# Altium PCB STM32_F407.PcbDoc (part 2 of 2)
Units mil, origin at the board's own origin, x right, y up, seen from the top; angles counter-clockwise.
Board outline 2935.42 x 3745.42 mil, 2 copper layers (TopLayer, BottomLayer); 75 components, 133 nets, 531 pads, 175 vias.
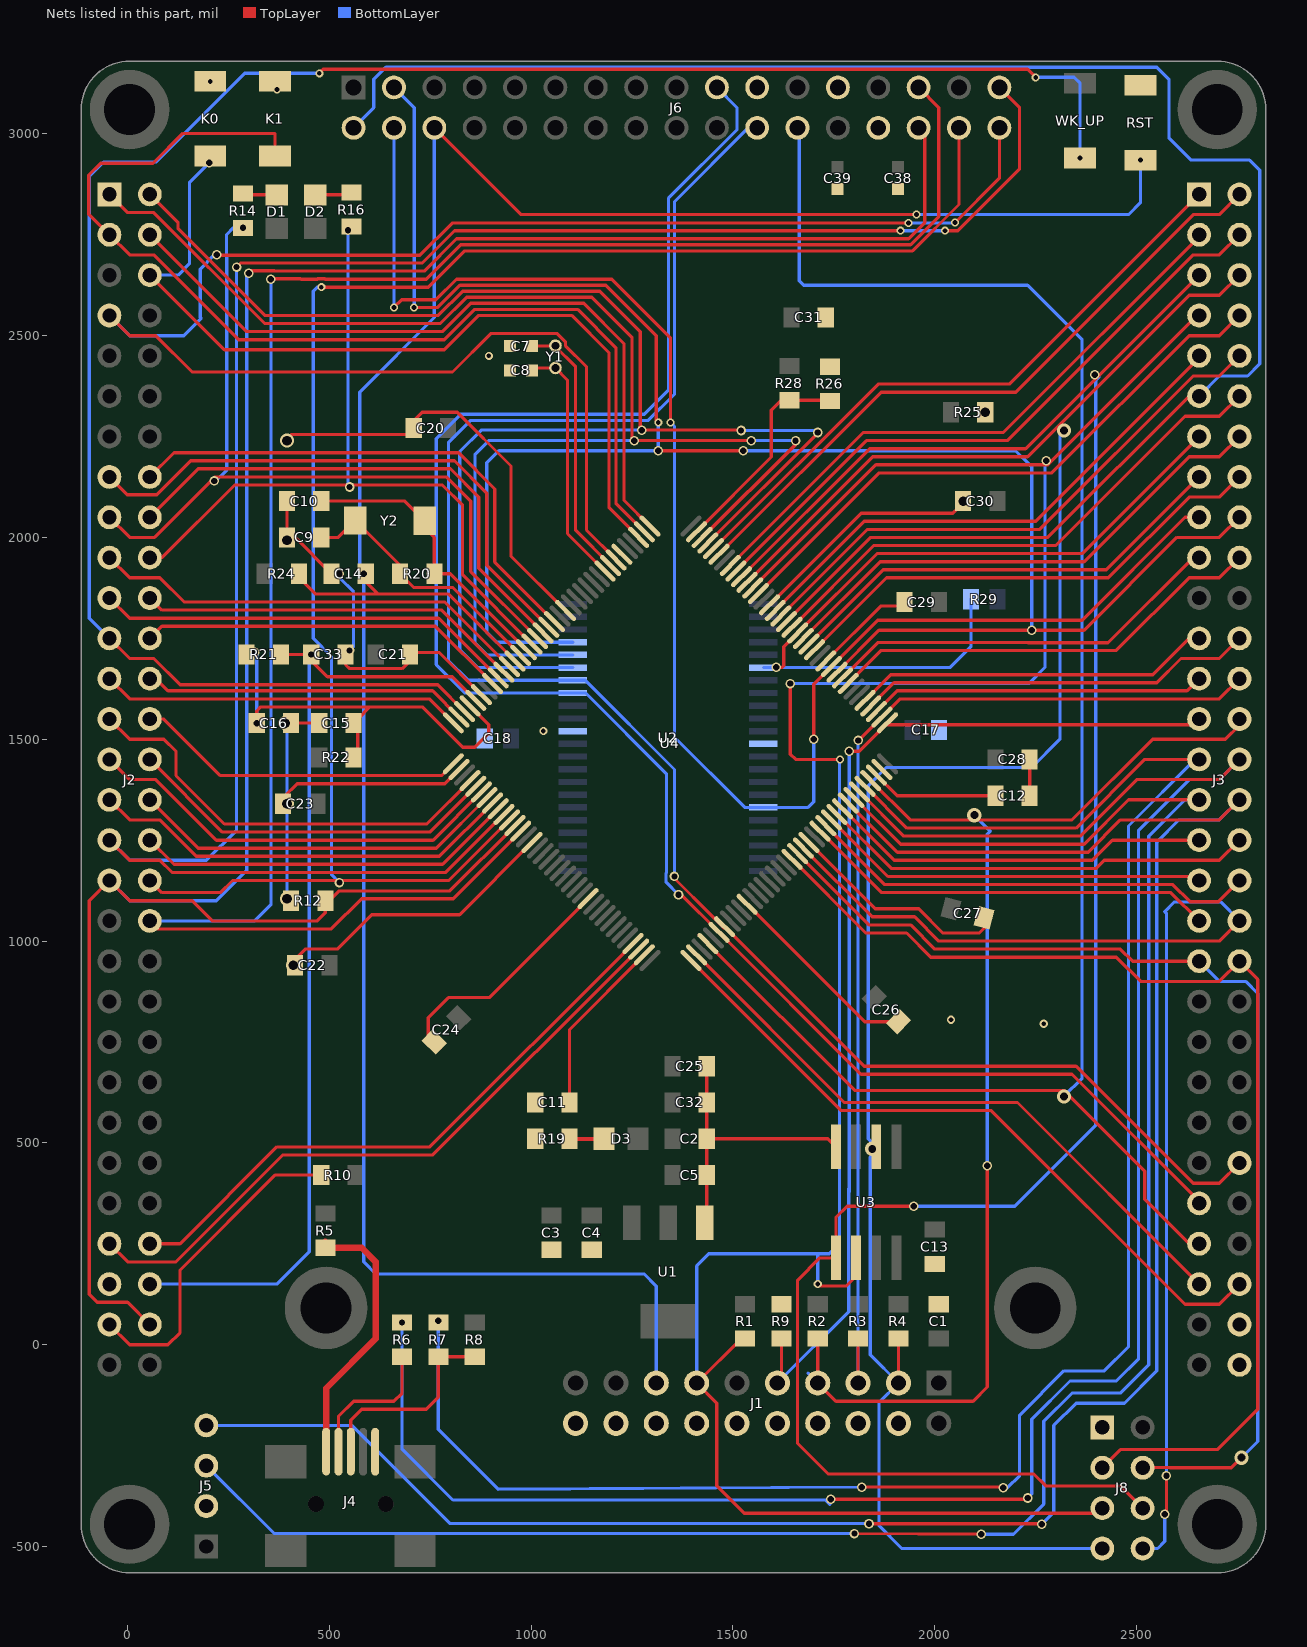
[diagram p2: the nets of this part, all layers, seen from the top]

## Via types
v1: diameter 23.62, hole 15.75, TopLayer to BottomLayer, 92 vias
v2: diameter 20, hole 12, TopLayer to BottomLayer, 62 vias
v3: diameter 35.43, hole 19.68, TopLayer to BottomLayer, 11 vias
v4: diameter 35.43, hole 23.62, TopLayer to BottomLayer, 10 vias

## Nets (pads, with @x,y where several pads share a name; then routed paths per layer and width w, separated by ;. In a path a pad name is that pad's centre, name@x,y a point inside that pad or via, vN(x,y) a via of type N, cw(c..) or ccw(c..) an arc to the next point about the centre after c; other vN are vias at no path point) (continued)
FSMC_D14: J3.51 J6.19 U2.37 U4.78 | length 4630.6
  TopLayer w8: v1(1365,1115) 1372.02,1115 U4.78@1465.4,1021.61 1817.02,670 2340,670 2655,355 J3.51@2655,350
  BottomLayer w8: v1(1365,1115) 1334.19,1145.81 1334.19,1168.62 1335,1169.43 1335,1415 1135.45,1614.55 U2.37@1102.91,1614.55 835.45,1614.55 765,1685 765,2245 825,2305 1280,2305 1340,2365 1340,2840 1510,3010 1510,3065 J6.19@1460,3115
FSMC_D15: J3.50 J6.22 U2.38 U4.79 | length 4576.3
  TopLayer w8: v1@1355,1155 1444.85,1065.15 1444.85,1065 U4.79@1476.82,1033.03 ; U4.79@1479.32,1035.53 1824.85,690 2350,690 2640,400 2705,400 J3.50@2755,450
  BottomLayer w8: v1(1355,1160) 1355,1425 1133.95,1646.05 U2.38@1102.91,1646.05 843.95,1646.05 795,1695 795,2235 850,2290 1290,2290 1355,2355 1355,2831.87 1538.13,3015 J6.22@1560,3015
FSMC_NBL0: J2.2 U2.39 U4.141 | length 3746.7
  TopLayer w8: J2.2@55,2850 125,2780 125,2765 340,2550 770,2550 830,2610 1170,2610 1270,2510 v1@1270,2265 ; v1(1274,2266) 1519,2266 v1(1520,2265) ; U4.141@1437.56,1986.23 1710,2258.66 v1(1710,2260)
  BottomLayer w8: U2.39@1102.91,1677.54 867.46,1677.54 823,1722 823,2213 876,2266 v1(1274,2266) ; v1(1520,2265) 1705,2265 v1(1710,2260)
FSMC_NBL1: J2.1 U2.40 U4.142 | length 3949.6
  TopLayer w8: J2.1@-45,2850 0,2805 65,2805 340,2530 775,2530 840,2595 1150,2595 1250,2495 v1@1250,2235 ; v1(1255,2240) v1(1545,2240) ; v1(1655,2240) v1@1655,2231.5 ; v1@1655,2231.5 1655,2230 1425.15,2000.15 U4.142@1423.64,2000.15 v1@1655,2231.5
  BottomLayer w8: U2.40@1102.91,1709.04 889.96,1709.04 861,1738 861,2206 895,2240 v1(1255,2240) ; v1(1545,2240) v1(1655,2240)
FSMC_NE3: J3.13 R29.1 U2.6 U4.125 | length 1966
  TopLayer w8: v1(1607,1678) 1622,1678 1626,1682 1626,1729.24 U4.125@1660.27,1763.52 1856.76,1960 2365,1960 J3.13@2655,2250
  BottomLayer w8: U2.6@1575.35,1677.54 2037.54,1677.54 2090,1730 R29.1@2090,1847
FSMC_NE4: J3.11 J6.2 U4.127 | length 4455.8
  TopLayer w8: U4.127@1632.44,1791.35 1841.08,2000 2280,2000 2630,2350 J3.11@2655,2350
  BottomLayer w8: J6.2@560,3015 610,3065 610,3135 640,3165 2550,3165 2580,3135 2580,2990 2635,2935 2780,2935 2805,2910 2805,2430 2775,2400 2705,2400 J3.11@2655,2350
FSMC_NOE: J3.18 J6.3 U2.41 U4.118 | length 5110.7
  TopLayer w8: v2(710,2570) 768.38,2570 823.38,2625 1185,2625 1310,2500 1310,2290 v2(1315,2285) ; v1(1315,2215) v1(1525,2215) ; U4.118@1757.71,1666.08 1861.63,1770 v1(2240,1770) 2370,1770 2600,2000 2705,2000 J3.18@2755,2050
  BottomLayer w8: J6.3@660,3115 710,3065 v2(710,2570) ; U2.41@1102.91,1740.54 914.46,1740.54 890,1765 890,2185 920,2215 v1(1315,2215) v2(1315,2285) ; v1(1525,2215) 2200,2215 2240,2175 v1(2240,1770)
FSMC_NWE: J3.17 J6.4 U2.17 U4.119 | length 4053.6
  TopLayer w8: v2(660,2570) 679,2589 764,2589 815,2640 1200,2640 1345,2495 v2(1345,2285) ; v1(1700,1500) 1700,1636.21 U4.119@1743.79,1680 1858.79,1795 1863.79,1795 2365,1795 2620,2050 J3.17@2655,2050
  BottomLayer w8: v2(660,2570) J6.4@660,3015 ; v2(1345,2285) 1355,2275 1355,1505 1528.91,1331.09 U2.17@1575.35,1331.09 1686.09,1331.09 1700,1345 v1(1700,1500)
GND: C1.1 C2.2 C3.2 C4.2 C5.2 C7.1 C8.1 C9.2 C10.2 C11.2 C12.2 C13.1 C14.1 C15.1 C16.1 C17.1 C18.1 C20.2 C21.2 C22.2 C23.2 C24.2 C25.2 C26.2 C27.2 C28.2 C29.2 C30.2 C31.2 C32.2 C33.2 C38.2 C39.2 J1.4 J1.6 J1.8 J1.10 J1.12 J1.14 J1.16 J1.18 J1.20 J2.55 J3.58 J3.60 J4.5 J5.2 J6.21 J6.25 J6.28 J8.1 K0.1 K1.1 R9.1 R12.2 R19.2 R25.2 R26.2 RST.2 U1.1 U2.12 U2.34 U3.4 U4.16 U4.31 U4.38 U4.51 U4.61 U4.83 U4.94 U4.107 U4.120 U4.130 | length 6936.3
  TopLayer w8: C23.2@387.5,1357.5 420,1390 785.66,1390 U4.38@820.93,1425.28 ; C10.2@395,2090 C9.2@395,2000 415,2000 C14.1@505,1910 ; v4@400,2250 405,2255 693,2255 C20.2@705,2267 ; C16.1@405,1540 C15.1@475,1540 ; C22.2@415,930 415,955 440,980 520,980 605,1065 822.56,1065 U4.51@1001.89,1244.32 ; C33.2@540,1710 540,1685 550,1675 680,1675 700,1695 C21.2@700,1705 ; C21.2@700,1710 C21.2@700,1705 ; C20.2@709,2271 C20.2@705,2267 ; C24.2@774.9,734.9 745,764.79 745,810 795,860 895.95,860 U4.61@1141.08,1105.13 ; U4.31@876.61,1610.4 772.02,1715 710,1715 C21.2@700,1705 ; U4.16@1085.4,1819.19 1083.94,1819.19 950,1953.13 950,2177 817,2310 730,2310 705,2285 C20.2@705,2267 ; U1.1@1430.55,302.05 1435,306.5 C5.2@1435,420 C2.2@1435,510 ; C25.2@1435,690 C32.2@1435,600 C2.2@1435,510 ; U4.83@1535,1091.21 1826.31,799.9 C26.2@1910.1,799.9 ; U4.130@1590.68,1833.11 1817.56,2060 2045,2060 C30.2@2060,2075 ; U4.94@1688.11,1244.32 1852.44,1080 1960,1080 2020,1020 2110,1020 2132.1,1042.1 C27.2@2132.1,1058 ; U4.120@1729.87,1693.92 1865.95,1830 C29.2@1925,1830 ; U3.4@1755,490 1735,510 C2.2@1435,510 ; C12.2@2235,1360 C28.2@2235,1450
  BottomLayer w8: v4(390,1540) 395,1535 v4(395,1340) v4(395,1105) ; v1(525,1910) 525,1900 560,1865 560,1730 v1(550,1720)
  other v2: 2270,795 2040,805 1030,1520 895,2450 370,3110 205,3130
  other v4: 410,940 395,1992.5 2070,2090 395,2240 2125,2310
KEY0: J2.6 K0.2 U4.3 | length 2155.5
  TopLayer w8: J2.6@55,2650 240,2465 785,2465 870,2550 1100,2550 1193,2457 1193,2073.5 U4.3@1266.36,2000.15
  BottomLayer w8: J2.6@55,2650 125,2650 153.28,2678.28 153.28,2879.28 v1(202,2928)
KEY1: J2.3 K1.2 U4.2 | length 2647
  TopLayer w8: K1.2@365,2944.96 365,3001 137,3001 63,2927 -67,2927 -96,2898 -96,2801 J2.3@-45,2750 5,2700 65,2700 275,2490 785,2490 860,2565 1115,2565 1210,2470 1210,2084.34 U4.2@1280.28,2014.07
LCD_BL: J3.53 J6.24 U4.76 | length 4632.3
  TopLayer w8: U4.76@1416.34,1015 U4.76@1437.56,993.77 1801.34,630 2320,630 2520,430 2520,360 2630,250 J3.53@2655,250
  BottomLayer w8: J6.24@1660,3015 1664,3011 1664,2636 1675,2625 2230,2625 2365,2490 2365,660 v3(2320,615)
LED0: J2.17 R14.2 U4.21 | length 2085.3
  TopLayer w8: J2.17@-45,2050 5,2000 67,2000 217,2150 790,2150 850,2090 850,1915.4 U4.21@1015.81,1749.6
  BottomLayer w8: v1(215,2140) 219,2140 245.81,2166.81 245.81,2699.43 245,2700.24 245,2750 262,2767 v1(286,2767)
LED1: J2.20 R16.2 U4.22 | length 1923.4
  TopLayer w8: J2.20@55,1950 85,1950 265,2130 780,2130 830,2080 830,1907.56 U4.22@1001.89,1735.68
  BottomLayer w8: v1(546,2761) 546,2129 v1(550,2125)
NetB1_1: 
NetC9_1: C9.1 R20.2 U4.24 Y2.2 | length 662.2
  TopLayer w8: C9.1@480,2000 522,2000 Y2.2@564,2042 675,1931 R20.2@675,1910 709,1876 805.89,1876 U4.24@974.05,1707.84
NetC10_1: C10.1 R20.1 U4.23 Y2.1 | length 722.3
  TopLayer w8: C10.1@480,2090 687,2090 Y2.1@736,2041 ; Y2.1@740,2041 740,2022 739,2021 760,2000 R20.1@760,1910 799.73,1910 U4.23@987.97,1721.76
NetC11_1: C11.1 U4.71 | length 442.7
  TopLayer w8: C11.1@1095,600 1095,780.66 U4.71@1280.28,965.93
NetC12_1: C12.1 U4.106 | length 316.1
  TopLayer w8: U4.106@1855.15,1411.36 1906.5,1360 C12.1@2150,1360
NetD1_2: D1.2 R14.1 | length 85.2
  TopLayer w8: R14.1@286,2852 289,2849 D1.2@370,2849
NetD2_2: D2.2 R16.1 | length 92.5
  TopLayer w8: D2.2@465,2849 549,2849 R16.1@555,2855
NetD3_2: D3.2 R19.1 | length 86
  TopLayer w10: R19.1@1095,510 D3.2@1181,510
NetJ2_57: J2.57 R10.1 | length 810.5
  TopLayer w8: J2.57@-45,50 5,0 100,0 130,30 130,185 365,420 R10.1@480,420
NetJ4_1: J4.1 R5.2 | length 666.7
  TopLayer w16: R5.2@490,255 505,240 580,240 615,205 615,15 492,-108 J4.1@492,-265
NetJ4_2: J4.2 R6.1 | length 359.2
  TopLayer w8: J4.2@522.5,-265.37 522.5,-177.5 560,-140 660,-140 680,-120 R6.1@680,-30
NetJ4_3: J4.3 R7.1 R8.1 | length 508.6
  TopLayer w8: J4.3@553,-265 553,-187 580,-160 740,-160 770,-130 R7.1@770,-30 R8.1@860,-30
NetR26_1: R26.1 R28.1 U4.143 | length 531
  TopLayer w8: U4.143@1409.72,2014.07 1595,2199.34 1595,2315 1620,2340 R28.1@1640,2340 R26.1@1738,2340
NRF_CE: J3.40 J8.3 U4.91 | length 2828.4
  TopLayer w8: U4.91@1646.35,1202.56 1828.92,1020 1930,1020 1990,960 2450,960 2510,900 2705,900 J3.40@2755,950 2800,905 2800,-160 2700,-260 2460,-260 J8.3@2415,-305
NRF_CS: J3.39 J8.4 U4.92 | length 2705.8
  TopLayer w8: U4.92@1660.27,1216.48 1836.76,1040 1940,1040 2000,980 2460,980 2490,950 J3.39@2655,950 ; J8.4@2515,-305 2515.81,-304.19 2582.62,-304.19 2583.43,-305 2735,-305 v3(2760,-280)
  BottomLayer w8: J3.39@2655,950 2705,900 2770,900 2800,870 2800,-240 v3(2760,-280)
NRF_IRQ: J3.38 J8.8 U4.93 | length 3043.8
  TopLayer w8: U4.93@1674.19,1230.4 1844.6,1060 1950,1060 2010,1000 2705,1000 J3.38@2755,1050 ; v1(2570,-420) 2574,-416 v1(2574,-325) 2574,-326 v1@2570,-330
  BottomLayer w8: J8.8@2515,-505 2552,-505 2570,-487 v1(2570,-420) ; v1(2574,-325) 2574,1069 2570,1073 2594,1097 2708,1097 J3.38@2755,1050
PA0/WK_UP: J2.23 U4.34 WK_UP.2 | length 4885
  TopLayer w8: J2.23@-45,1750 5,1700 65,1700 130,1635 768.5,1635 U4.34@834.85,1568.64 ; v2(475,3150) 485,3160 2230,3160 v2(2250,3140)
  BottomLayer w8: J2.23@-45,1750 -95,1800 -95,2895 -60,2930 70,2930 290,3150 v2(475,3150) ; v2(2250,3140) 2345,3140 2360,3125 v2(2360,2939.96)
PA1: J2.26 U4.35 | length 805.4
  TopLayer w8: J2.26@55,1650 70,1650 100,1620 755.66,1620 U4.35@820.93,1554.72
PA2: J2.25 U4.36 | length 897.2
  TopLayer w8: J2.25@-45,1650 5,1600 747.82,1600 U4.36@807.01,1540.81
PA3: J2.28 U4.37 | length 822.1
  TopLayer w8: J2.28@55,1550 90,1550 230,1410 777.82,1410 U4.37@807.01,1439.19
PA4: J2.27 U4.40 | length 1081.1
  TopLayer w8: J2.27@-45,1550 5,1500 90,1500 120,1470 120,1410 240,1290 741.34,1290 U4.40@848.77,1397.44
PA5: J2.30 U4.41 | length 929.3
  TopLayer w8: J2.30@55,1450 235,1270 749.18,1270 U4.41@862.69,1383.52
PA6: J2.29 U4.42 | length 1054
  TopLayer w8: J2.29@-45,1450 5,1400 70,1400 220,1250 757.01,1250 U4.42@876.61,1369.6
PA7: J2.32 U4.43 | length 937.3
  TopLayer w8: J2.32@55,1350 175,1230 764.85,1230 U4.43@890.53,1355.68
PA8: J3.33 U4.100 | length 957
  TopLayer w8: U4.100@1771.63,1327.84 1899.47,1200 2390,1200 2440,1250 J3.33@2655,1250
PA9/TXD1: J3.32 J5.4 U4.101 | length 5372.1
  TopLayer w8: U4.101@1785.55,1341.76 1907.31,1220 2380,1220 2460,1300 2705,1300 J3.32@2755,1350 ; v1(1837,-444) 2264,-444 v1(2265,-445)
  BottomLayer w8: J5.4@195,-200 555,-200 798,-443 1836,-443 v1(1837,-444) ; v1(2265,-445) 2295,-415 2295,-200 2350,-145 2470,-145 2550,-65 2550,1245 2605,1300 2705,1300 J3.32@2755,1350
PA10/RXD1: J3.31 J5.3 U4.102 | length 5119.9
  TopLayer w8: U4.102@1799.47,1355.68 1915.15,1240 2370,1240 2480,1350 J3.31@2655,1350 ; v1(1801,-468) v1(2115,-470)
  BottomLayer w8: J5.3@195,-300 363,-468 v1(1801,-468) ; v1(2115,-470) 2195,-470 2270,-395 2270,-190 2340,-120 2460,-120 2530,-50 2530,1260 2620,1350 J3.31@2655,1350
PA11/USB_DM: J3.30 R6.2 U4.103 | length 5143.2
  TopLayer w8: v1(1742,-383) v1@2230,-383 ; U4.103@1813.39,1369.6 1922.99,1260 2360,1260 2500,1400 2705,1400 J3.30@2755,1450
  BottomLayer w8: v1(680,55) 680,-259 806,-385 1729,-385 1740,-396 ; v1(2230,-380) 2240,-370 2240,-185 2335,-90 2450,-90 2505,-35 2505,1275 2630,1400 2705,1400 J3.30@2755,1450
PA12/USB_DP: J3.29 R7.2 U4.104 | length 4748.3
  TopLayer w8: v1(1819,-353) 2168,-353 v1(2170,-355) ; U4.104@1827.31,1383.52 1930.82,1280 2350,1280 2520,1450 J3.29@2655,1450
  BottomLayer w8: v1(770,59) 770,-210 918,-358 v1(1819,-353) ; v1(2170,-355) 2180,-355 2210,-325 2210,-175 2320,-65 2420,-65 2480,-5 2480,1285 2645,1450 J3.29@2655,1450
PA13/TMS: J1.7 J3.28 R2.2 U4.105 | length 3100.1
  TopLayer w8: R2.2@1710,15 J1.7@1710,-95 1755,-140 2095,-140 2130,-105 v1(2130,443) ; U4.105@1841.23,1397.44 1938.66,1300 2340,1300 2540,1500 2720,1500 2755,1535 J3.28@2755,1550
  BottomLayer w8: 1686,-71 J1.7@1710,-95 ; v3(2098,1312) 2137.64,1272.36 2130,1264.72 v1(2130,443)
PA14/TCK: J1.9 J3.27 R9.2 U4.109 | length 2661.8
  TopLayer w8: J1.9@1610,-95 1620,-85 R9.2@1620,15 ; v1(1788,1470) 1812.43,1470 1882.99,1540.55 U4.109@1882.99,1540.81 ; U4.109@1882.99,1535.81 2640.81,1535.81 J3.27@2655,1550
  BottomLayer w8: J1.9@1610,-95 1787,82 1787,386 ; 1788,379 v1(1788,1470)
PA15/TDI: J1.5 J3.26 R3.2 U4.110 | length 2710.4
  TopLayer w8: J1.5@1810,-95 R3.2@1810,15 ; v1(1810,1497) 1811.34,1497 U4.110@1869.07,1554.72 1914.34,1600 2705,1600 J3.26@2755,1650
  BottomLayer w8: J1.5@1810,-95 v1(1810,1497)
PB0: J2.33 J6.33 U4.46 | length 5095.1
  TopLayer w8: J2.33@-45,1250 5,1200 80,1200 110,1170 788.37,1170 U4.46@932.29,1313.92 ; v1(270,2670) 280,2680 730,2680 810,2760 v2(1915,2760) ; v2(2025,2760) 2056.87,2760 2210,2913.13 2210,3065 J6.33@2160,3115
  BottomLayer w8: J2.33@-45,1250 5,1200 195,1200 270,1275 v1(270,2670) ; v2(1915,2760) v2(2025,2760)
PB1: J2.36 J6.32 U4.47 | length 4349.2
  TopLayer w8: J2.36@55,1150 85,1120 230,1120 260,1150 796.21,1150 U4.47@946.21,1300 ; v2(480,2620) 745,2620 835,2710 1945,2710 2060,2825 J6.32@2060,3015
  BottomLayer w8: v2(480,2620) 470,2620 460,2610 460,1750 505,1705 505,1165 v1(525,1145)
PB2/BOOT1: J2.35 J2.58 J6.30 R12.1 U4.48 | length 6236
  TopLayer w8: J2.58@55,50 0,105 -75,105 -95,125 -95,1100 J2.35@-45,1150 5,1100 160,1100 210,1050 470,1050 490,1070 R12.1@490,1090 ; v1(300,2655) 305.81,2660.81 363.62,2660.81 364.43,2660 735,2660 815,2740 1935,2740 1975,2780 1975,3000 J6.30@1960,3015 ; R12.1@490,1100 R12.1@490,1090 ; U4.48@960.13,1286.08 798.24,1124.19 524.19,1124.19 R12.1@490,1090
  BottomLayer w8: J2.35@-45,1150 5,1100 220,1100 295,1175 295,1705.57 294.19,1706.38 294.19,1723.62 295,1724.43 295,2650 v1(300,2655)
PB3/TDO: J1.13 J3.7 J8.5 R1.2 U3.6 U4.133 | length 6363.6
  TopLayer w8: R1.2@1530,15 1520,15 J1.13@1410,-95 1460,-145 1460,-350 1527.81,-417.81 2402.19,-417.81 J8.5@2415,-405 ; U4.133@1548.92,1874.87 1854.05,2180 2280,2180 2650,2550 J3.7@2655,2550 ; v1(1642,1638) 1642,1463 1655,1450 v2(1765,1450) ; v2(1710,150) 1715,145 1780,145 1805,170 U3.6@1805,215
  BottomLayer w8: J1.13@1410,-95 1410,195 1440,225 1710,225 ; v1(1642,1638) 2233,1638 2273,1678 v1@2273,2180 ; v2(1710,150) 1710,225 ; v2(1765,1450) 1764,1450 1764,250 1739,225 1710,225
  other v1: 2276,2190
PB4/TRST: J1.3 J3.6 J8.7 R4.2 U3.2 U4.134 | length 5430.7
  TopLayer w8: U4.134@1535,1888.79 1846.21,2200 2230,2200 2630,2600 2705,2600 J3.6@2755,2650 ; J1.3@1910,-95 R4.2@1910,15
  BottomLayer w8: v3(1845,485) v3@1860,485 ; v3@2310,2270 2310,1500 2240,1430 1880,1430 1835,1385 1835,510 v3@1860,485 ; J8.7@2415,-505 1918,-505 1862,-449 1862,-143 J1.3@1910,-95 1840,-25 1840,465 v3@1860,485
  other v3: 2320,2265
PB5: J3.5 J8.6 U3.5 U4.135 | length 5583.7
  TopLayer w8: U4.135@1521.08,1902.71 1838.37,2220 2225,2220 J3.5@2655,2650 ; v1(1948,343) 1783,343 1755,315 U3.5@1755,215 1715,215 1660,160 1660,-245 1735.5,-320.5 2245.5,-320.5 2275,-350 2460,-350 J8.6@2515,-405
  BottomLayer w8: v1(1948,343) 2198,343 2399,544 2399,2390 2407,2398
  other v1: 2396,2403
PB6: J3.4 U4.136 | length 1593
  TopLayer w8: U4.136@1507.16,1916.63 1830.53,2240 2180,2240 2640,2700 2705,2700 J3.4@2755,2750
PB7: J3.3 U4.137 | length 1504.1
  TopLayer w8: U4.137@1493.24,1930.55 1822.69,2260 2170,2260 2655,2745 J3.3@2655,2750
PB8: J3.2 U4.139 | length 1658.9
  TopLayer w8: U4.139@1465.4,1958.39 1867.01,2360 2200.41,2360 2640.41,2800 2705,2800 J3.2@2755,2850
PB9: J3.1 U4.140 | length 1567.1
  TopLayer w8: U4.140@1451.48,1972.31 1451.74,1972.31 1859.43,2380 2185,2380 J3.1@2655,2850
PB10: J2.54 U4.69 | length 1505.5
  TopLayer w8: J2.54@55,250 130,250 370,490 748.66,490 U4.69@1252.44,993.77
PB11: J2.53 U4.70 | length 1651
  TopLayer w8: J2.53@-45,250 0,205 120,205 385,470 756.5,470 U4.70@1266.36,979.85
PB12: J3.56 U4.73 | length 1732.8
  TopLayer w8: U4.73@1395.81,952.01 1767.82,580 2140,580 2620,100 2705,100 J3.56@2755,150
PB13: J3.55 U4.74 | length 1583.2
  TopLayer w8: U4.74@1409.72,965.93 1775.66,600 2205,600 J3.55@2655,150
PC0: J2.19 U4.26 | length 1103
  TopLayer w8: J2.19@-45,1950 5,1900 80,1900 140,1840 786.21,1840 U4.26@946.21,1680
PC1: J2.22 U4.27 | length 953.5
  TopLayer w8: J2.22@55,1850 85,1820 778.37,1820 U4.27@932.29,1666.08
PC2: J2.21 U4.28 | length 1045.3
  TopLayer w8: J2.21@-45,1850 5,1800 770.53,1800 U4.28@918.37,1652.16
PC3: J2.24 U4.29 | length 920.6
  TopLayer w8: J2.24@55,1750 85,1780 762.69,1780 U4.29@904.45,1638.24
PC4: J2.31 U4.44 | length 1062
  TopLayer w8: J2.31@-45,1350 5,1300 80,1300 170,1210 772.69,1210 U4.44@904.45,1341.76
PC5: J2.34 U4.45 | length 945.3
  TopLayer w8: J2.34@55,1250 115,1190 780.53,1190 U4.45@918.37,1327.84
PC6: J3.37 U4.96 | length 1031.1
  TopLayer w8: U4.96@1715.95,1272.16 1868.11,1120 2585,1120 J3.37@2655,1050
PC7: J3.36 U4.97 | length 1125
  TopLayer w8: U4.97@1729.87,1286.08 1875.95,1140 2590,1140 2632.5,1097.5 2702.5,1097.5 2735,1130 J3.36@2755,1150
PC8: J3.35 U4.98 | length 973.3
  TopLayer w8: U4.98@1743.79,1300 1883.79,1160 2645,1160 J3.35@2655,1150
PC9: J3.34 U4.99 | length 1081.8
  TopLayer w8: U4.99@1757.71,1313.92 1891.63,1180 2400,1180 2420,1200 2705,1200 J3.34@2755,1250
PC10: J3.25 U4.111 | length 833.6
  TopLayer w8: U4.111@1855.15,1568.64 1906.5,1620 2625,1620 J3.25@2655,1650
PC11: J3.24 U4.112 | length 983.1
  TopLayer w8: U4.112@1841.23,1582.56 1898.66,1640 2550,1640 2610,1700 2705,1700 J3.24@2755,1750
PC12: J3.23 U4.113 | length 891.3
  TopLayer w8: U4.113@1827.31,1596.48 1890.82,1660 2540,1660 2630,1750 J3.23@2655,1750
PC13: J2.7 J6.34 U4.7 | length 4425.4
  TopLayer w8: J2.7@-45,2550 5,2500 70,2500 160,2410 805,2410 900,2505 1065,2505 1084.75,2485.25 1084.75,2475.25 1137,2423 1137,2018.15 U4.7@1210.68,1944.47 ; v1(220.81,2700) 216.62,2700 215.81,2699.19 724.19,2699.19 804,2779 v2(1935,2779) ; v2(2050,2780) 2160,2890 J6.34@2160,3015
  BottomLayer w8: J2.7@-45,2550 5,2500 139,2500 182,2543 180,2545 180,2665 215,2700 v1(220.81,2700) ; v2(1935,2779) 2049,2779 v2(2050,2780)
PC14: C7.2 U4.8 Y1.2 | length 657.5
  TopLayer w8: C7.2@1002,2474 1059,2474 1110,2423 1110,2017.31 U4.8@1196.76,1930.55
PC15: C8.2 U4.9 Y1.1 | length 614.7
  TopLayer w8: C8.2@1002,2414 1008,2420 Y1.1@1060,2420 1090,2390 1090,2009.47 U4.9@1182.84,1916.63
PD2: J3.20 U4.116 | length 1098.6
  TopLayer w8: U4.116@1785.55,1638.24 1867.31,1720 2450,1720 2630,1900 2705,1900 J3.20@2755,1950
PD3: J3.19 U4.117 | length 1007.4
  TopLayer w8: U4.117@1771.63,1652.16 1859.47,1740 2230.57,1740 2231.38,1739.19 2429.19,1739.19 2640,1950 J3.19@2655,1950
PD6: J3.16 U4.122 | length 1230.4
  TopLayer w8: U4.122@1702.03,1721.76 1880.27,1900 2430,1900 2630,2100 2705,2100 J3.16@2755,2150
PD7: J3.15 U4.123 | length 1138.5
  TopLayer w8: U4.123@1688.11,1735.68 1872.44,1920 2425,1920 J3.15@2655,2150
PE2: J2.4 U4.1 | length 1823.4
  TopLayer w8: J2.4@55,2750 295,2510 780,2510 850,2580 1130,2580 1230,2480 1230,2092.18 U4.1@1294.19,2027.99
PF6: J2.16 U4.18 | length 1306.9
  TopLayer w8: J2.16@55,2150 115,2210 820,2210 910,2120 910,1938.92 U4.18@1057.56,1791.35
PF7: J2.15 U4.19 | length 1417.4
  TopLayer w8: J2.15@-45,2150 -1,2106 72,2106 156,2190 810,2190 890,2110 890,1931.08 U4.19@1043.65,1777.44
PF8: J2.18 U4.20 | length 1296.3
  TopLayer w8: J2.18@55,2050 175,2170 800,2170 870,2100 870,1923.24 U4.20@1029.73,1763.52
PF11: J2.38 J6.29 U4.49 | length 4955.5
  TopLayer w8: J2.38@55,1050 75,1030 505,1030 580,1105 806.89,1105 U4.49@974.05,1272.16 ; v1(355,2640) 355.81,2640.81 428.62,2640.81 429.43,2640 470.57,2640 471.38,2640.81 488.62,2640.81 489.43,2640 740,2640 825,2725 1940,2725 2010,2795 2010,3065 J6.29@1960,3115
  BottomLayer w8: J2.38@55,1050 315,1050 355,1090 v1(355,2640)
PG9: J3.14 U4.124 | length 1288.1
  TopLayer w8: U4.124@1674.19,1749.6 1864.6,1940 2370,1940 2630,2200 2705,2200 J3.14@2755,2250
PG11: J3.12 U4.126 | length 1345.8
  TopLayer w8: U4.126@1646.35,1777.44 1848.92,1980 2300,1980 2620,2300 2705,2300 J3.12@2755,2350
PG13: J3.10 U4.128 | length 1403.5
  TopLayer w8: U4.128@1618.52,1805.27 1833.24,2020 2260,2020 2640,2400 2705,2400 J3.10@2755,2450
PG14: J3.9 U4.129 | length 1314.6
  TopLayer w8: U4.129@1604.6,1819.19 1825.4,2040 2250,2040 2655,2445 J3.9@2655,2450
PG15: J3.8 U4.132 | length 1477.6
  TopLayer w8: U4.132@1562.84,1860.95 1861.89,2160 2290,2160 2630,2500 2705,2500 J3.8@2755,2550
RESET: C14.2 J1.15 J6.6 R24.1 RST.1 U4.25 | length 6500
  TopLayer w8: R24.1@440,1910 440,1885 465,1860 620,1860 ; C14.2@592.73,1887.27 620,1860 ; J6.6@760,3015 975,2800 v2(1955,2800) ; U4.25@960.13,1693.92 794.05,1860 620,1860
  BottomLayer w8: J6.6@760,3015 760,2545 575,2360 575,1920 v1(585,1910) 585,205 615,175 1280,175 1310,145 J1.15@1310,-95 ; v2(1955,2800) 2480,2800 2510,2830 v2(2510,2935)
VBAT: U4.6
VDDA: C15.2 C16.2 R21.2 R22.1 U4.33 | length 1068.3
  TopLayer w8: v1(320,1540) 320,1570 330,1580 600,1580 ; R22.1@565,1465 570,1470 570,1550 600,1580 ; U4.33@848.77,1582.56 895,1536.34 895,1515 860,1480 830,1480 730,1580 600,1580
  BottomLayer w8: v1(315,1715) 320,1720 v1(320,1540)
VREF+: C33.1 J2.56 R21.1 U4.32 | length 2456.5
  TopLayer w8: R21.1@380,1720 390,1710 v1(455,1710) 455,1695 495,1655 804.18,1655 U4.32@862.69,1596.48
  BottomLayer w8: J2.56@55,150 370,150 450,230 450,1330.57 449.19,1331.38 449.19,1348.62 450,1349.43 450,1710 v1(455,1710)
pads on no net: J1.11 J1.17 J1.19 J4. J4.4 J6.31 U1.4

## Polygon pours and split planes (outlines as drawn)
GND on BottomLayer "TopLayer-No Net" (solid, pour order 6): -125,3195 2810,3195 2830,3175 2830,-585 -105,-585 -120,-570
GND on TopLayer "TopLayer-No Net" (solid, pour order 8): -115,3180 2820,3180 2820,-565 2830,-575 2825,-570 -115,-570

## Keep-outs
KeepOutLayer:
  the board outline again, w8

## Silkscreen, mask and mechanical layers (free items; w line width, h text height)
TopOverlay:
  region: 2345,-155 2280,-155 2280,-215 2345,-215
  text "K0" at 225,3055 h35 r180
  text "K1" at 385,3055 h35 r180
  text "UP" at 2380,3040 h35 r180
  text "RS" at 2530,3040 h35 r180
  text "STM32F407ZET6" at 1510,2930 h80 r180
  text "PE1" at 170,2880 h32 r225
  text "PE0" at 235,2865 h32 r225
  text "PB9" at 2455,2825 h32 r180
  text "PB8" at 2574.75,2824.75 h32 r180
  text "PE3" at 170,2790 h32 r225
  text "PE2" at 240,2785 h32 r225
  text "PB7" at 2455,2760 h32 r180
  text "PB6" at 2575,2760 h32 r180
  text "PE5" at 170,2700 h32 r225
  text "PE4" at 240,2690 h32 r225
  text "PB5" at 2450,2665 h32 r180
  text "PB4" at 2575,2665 h32 r180
  text "PB3" at 2440,2565 h32 r180
  text "PG15" at 2580,2565 h32 r180
  text "PC13" at 230,2560 h32 r180
  text "PE6" at 330,2560 h32 r180
  text "PF1" at 205,2465 h32 r180
  text "PG14" at 2445,2465 h32 r180
  text "PG13" at 2580,2465 h32 r180
  text "PF0" at 330,2460 h32 r180
  text "PF3" at 210,2365 h32 r180
  text "PF2" at 330,2365 h32 r180
  text "PG12" at 2435,2365 h32 r180
  text "PG11" at 2575,2365 h32 r180
  text "PF5" at 205,2265 h32 r180
  text "PF4" at 320,2263.58 h32 r180
  text "PG10" at 2425,2260 h32 r180
  text "PG9" at 2570,2260 h32 r180
  text "PF7" at 205,2175 h32 r180
  text "PF6" at 310,2175 h32 r180
  text "PD6" at 2570,2165 h32 r180
  text "PD7" at 2450,2160 h32 r180
  text "PF9" at 170,2105 h32 r225
  text "PF8" at 225,2095 h32 r225
  text "PD5" at 2450,2065 h32 r180
  text "PD4" at 2570,2065 h32 r180
  text "PC0" at 175,1990 h32 r225
  text "PF10" at 235,1970 h32 r225
  text "PD3" at 2435,1970 h32 r180
  text "PD2" at 2570,1970 h32 r180
  text "PC2" at 195,1865 h32 r225
  text "PC1" at 260,1865 h32 r225
  text "PD1" at 2435,1865 h32 r180
  text "PD0" at 2570,1865 h32 r180
  text "PA0" at 170,1780 h32 r225
  text "PC3" at 235,1770 h32 r225
  text "PC12" at 2440,1765 h32 r180
  text "PC11" at 2570,1765 h32 r180
  text "PC10" at 2425,1670 h32 r180
  text "PA2" at 195,1660 h32 r180
  text "PA1" at 295,1660 h32 r180
  text "PA15" at 2570,1660 h32 r180
  text "PA14" at 2425,1570 h32 r180
  text "PA13" at 2580,1570 h32 r180
  text "PA4" at 200,1550 h32 r180
  text "PA3" at 305,1550 h32 r180
  text "PA6" at 205,1460 h32 r180
  text "PA12" at 2460,1460 h32 r180
  text "PA11" at 2580,1460 h32 r180
  text "PA5" at 325,1455 h32 r180
  text "PC4" at 205,1365 h32 r180
  text "PA7" at 325,1365 h32 r180
  text "PA10" at 2460,1365 h32 r180
  text "PA9" at 2580,1365 h32 r180
  text "PA8" at 2460,1270 h32 r180
  text "PC9" at 2580,1270 h32 r180
  text "PB0" at 210,1260 h32 r180
  text "PC5" at 335,1260 h32 r180
  text "PB1" at 335,1165 h32 r180
  text "PC8" at 2460,1165 h32 r180
  text "PC7" at 2580,1165 h32 r180
  text "PB2" at 220,1160 h32 r180
  text "PC6" at 2465,1070 h32 r180
  text "PG8" at 2580,1070 h32 r180
  text "PF12" at 225,1065 h32 r180
  text "PF11" at 360,1065 h32 r180
  text "PF14" at 225,970 h32 r180
  text "PG7" at 2465,965 h32 r180
  text "PG6" at 2580,965 h32 r180
  text "PF13" at 360,960 h32 r180
  text "PG0" at 210,870 h32 r180
  text "PF15" at 345,870 h32 r180
  text "PG5" at 2465,865 h32 r180
  text "PG4" at 2580,865 h32 r180
  text "PE7" at 215,770 h32 r180
  text "PG1" at 340,770 h32 r180
  text "PG2" at 2580,770 h32 r180
  text "PG3" at 2447.57,767.17 h32 r180
  text "STM32F4XX" at 2120,670 h100 r180
  text "PD14" at 2585,670 h32 r180
  text "PD15" at 2433.57,668.04 h32 r180
  text "PE9" at 210,660 h32 r180
  text "PE8" at 340,660 h32 r180
  text "PD12" at 2585,570 h32 r180
  text "PD13" at 2431.65,568.35 h32 r180
  text "PE11" at 215,565 h32 r180
  text "PE10" at 340,565 h32 r180
  text "PD11" at 2438,470 h32 r180
  text "PD10" at 2585,470 h32 r180
  text "PE13" at 225,465 h32 r180
  text "PE12" at 350,465 h32 r180
  text "PE15" at 225,370 h32 r180
  text "PE14" at 350,370 h32 r180
  text "PD9" at 2438,370 h32 r180
  text "PD8" at 2580,370 h32 r180
  text "PB15" at 2450,275 h32 r180
  text "PB14" at 2580,275 h32 r180
  text "PB11" at 220,270 h32 r180
  text "PB10" at 350,270 h32 r180
  text "GND" at 210,180 h32 r180
  text "VREF+" at 375,180 h32 r180
  text "PB13" at 2450,180 h32 r180
  text "PB12" at 2590,180 h32 r180
  text "3V3" at 2470,80 h35 r180
  text "GND" at 2590,80 h32 r180
  text "BT0" at 215,65 h32 r180
  text "BT1" at 340,65 h32 r180
  text "5V" at 2460,-20 h35 r180
  text "GND" at 2585,-25 h32 r180
  text "3V3" at 215,-40 h32 r180
  text "3V3" at 340,-40 h32 r180
  text "TX" at 320,-175 h32 r180
  text "1" at 2330,-245 h35 r90
  text "RX" at 320,-280 h32 r180
  text "GND" at 340,-390 h32 r180
  text "JTAG/SWD" at 1315,-470 h80 r180
  text "5V" at 310,-490 h32 r180
  text "NRF2401" at 2325,-530 h65 r90
BottomOverlay:
  text "BAT" at 2075,2230 h78.74 r180
  text "1507" at 1385,840 h45 r180
  text "V2.0" at 980,835 h45 r180
  text "STM32_F4XX" at 970,710 h60 r180
  text "STM32F4XX" at 1135,100 h160 r180

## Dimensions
2700,3180.21 to 2700,-565.21 on TopOverlay
-115.21,-445 to 2820.21,-445 on TopOverlay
